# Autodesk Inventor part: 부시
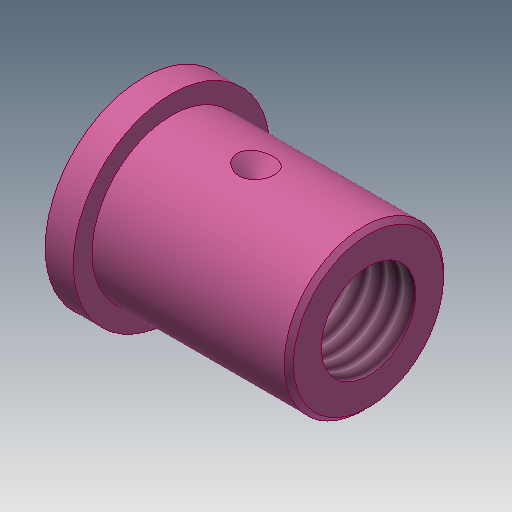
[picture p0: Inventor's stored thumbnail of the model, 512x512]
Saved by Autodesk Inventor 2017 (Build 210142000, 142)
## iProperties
Created: 2019-04
Part Number: 부시
Material: 강철, 연강
Document SubType Name: Modeling
Designer: mduedu
Density: 1 g/cm^3
Appearance: 분홍색
Author: mduedu
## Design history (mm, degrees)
sketch "스케치1"
  geometry: L1 (0, 0)-(3, 0); L2 (3, 0)-(3, 10.5); L3 (3, 10.5)-(0, 10.5); L4 (0, 10.5)-(0, 0); L5 (3, 0)-(24, 0); L6 (24, 0)-(24, 8.5); L7 (24, 8.5)-(3, 8.5); L8 (3, 8.5)-(3, 0)
  constraints: 16 end point, 4 parallel, 2 horizontal, 2 perpendicular
  dimensions: "d0" = 3 distance of L2.end L3.end; "d2" = 24 distance between parallel lines of L6 L4; "d3" = 17 diameter of L7 L5; "d4" = 21 diameter of L3 L1
revolve "회전1" sketch "스케치1" stored, may be unused: angle "d5" = 90 deg
sketch "스케치2"
  geometry: L1 (3, 8.5)-(24, 8.5) reference; L2 (12, 8.5)-(12, 6.5); L3 (12, 6.5)-(14, 8.5); L4 (0, -10.5)-(0, 10.5) reference; 1 further point
  constraints: 4 end point, 2 point on line, 1 perpendicular
  dimensions: "d6" = 12 distance from line of L2.start L4; "d7" = 2 distance of L2.start L3.end; "d8" = 45 deg angle of L3 L2
revolve "회전2" sketch "스케치2" stored, may be unused: angle "d9" = 90 deg
hole "구멍1" diameter "d12" = 10.106; stored, may be unused: countersink angle "d16" = 90 deg, drill point angle "d18" = 118 deg; dims "d10" = 10, "d11" = 10, "d13" = 39, "d14" = 4, "d15" = 2, "d17" = 8
chamfer "모따기1" distance "d19" = 0.5; stored, may be unused: second distance "d20" = 2, angle "d21" = 45 deg
node "작업점1"
  node "작업 평면1"
  node "작업축1"
node "솔리드1"
